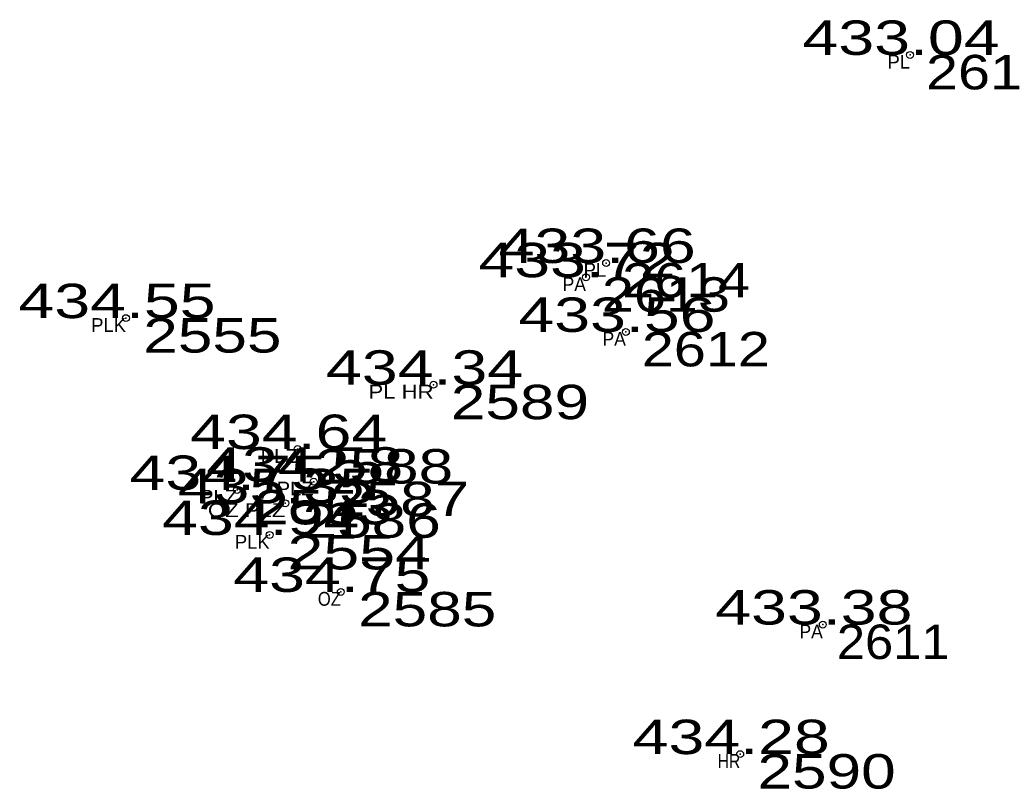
# Model space of a CAD drawing. Extents: x -639390 to -639074, y -1138747 to -1138358.
# Drawn here: x -639365.5 to -639343.8, y -1138399.35 to -1138382.61 of the extents above; entities that cross this region are included whole.
import ezdxf
from ezdxf.enums import TextEntityAlignment as Align

# ---------------------------------------------------------------- set-up
doc = ezdxf.new("R2010")
doc.units = 0
doc.header["$LTSCALE"] = 0.3
doc.header["$PDMODE"] = 32
doc.header["$PDSIZE"] = 0.15
for name, color, linetype in [('11', 7, 'Continuous'), ('12', 7, 'Continuous'), ('13', 7, 'Continuous'), ('57', 7, 'Continuous')]:
    doc.layers.add(name, color=color, linetype=linetype)

msp = doc.modelspace()

# ---------------------------------------------------------------- linework, layer by layer
at = {"layer": '11'}
for p in [(-639346.11, -1138383.37), (-639352.73, -1138387.9), (-639353.17, -1138388.21), (-639363.19, -1138389.1), (-639352.3, -1138389.4), (-639356.49, -1138390.55), (-639359.45, -1138391.95), (-639359.1, -1138392.66), (-639360.77, -1138392.84), (-639359.72, -1138393.13), (-639360.06, -1138393.82), (-639358.51, -1138395.06), (-639348.01, -1138395.77), (-639349.81, -1138398.59)]:
    msp.add_point(p, dxfattribs=at)

# ---------------------------------------------------------------- texts
at = {"layer": '12', "width": 1.4}
for s, p in [('433.04 ', (-639346.11, -1138383.37)), ('433.66 ', (-639352.729, -1138387.9)), ('433.72 ', (-639353.17, -1138388.21)), ('434.55 ', (-639363.19, -1138389.1)), ('433.56 ', (-639352.299, -1138389.4)), ('434.34 ', (-639356.49, -1138390.55)), ('434.64 ', (-639359.45, -1138391.95)), ('434.58 ', (-639359.1, -1138392.66)), ('434.75 ', (-639360.77, -1138392.84)), ('435.35 ', (-639359.72, -1138393.13)), ('434.94 ', (-639360.06, -1138393.82)), ('434.75 ', (-639358.51, -1138395.06)), ('433.38 ', (-639348.01, -1138395.77)), ('434.28 ', (-639349.81, -1138398.59))]:
    msp.add_text(s, height=0.75, dxfattribs=at).set_placement(p, align=Align.CENTER)
at = {"layer": '13'}
for s, width, p in [(' 2615', 1.25, (-639346.11, -1138384.12)), (' 2614', 1.25, (-639352.73, -1138388.65)), (' 2613', 1.25, (-639353.17, -1138388.96)), (' 2555', 1.35, (-639363.19, -1138389.85)), (' 2612', 1.25, (-639352.3, -1138390.15)), (' 2589', 1.35, (-639356.49, -1138391.3)), (' 2588', 1.35, (-639359.45, -1138392.7)), (' 2587', 1.35, (-639359.1, -1138393.41)), (' 2553', 1.35, (-639360.77, -1138393.59)), (' 2586', 1.35, (-639359.72, -1138393.88)), (' 2554', 1.4, (-639360.06, -1138394.57)), (' 2585', 1.35, (-639358.51, -1138395.81)), (' 2611', 1.1, (-639348.01, -1138396.52)), (' 2590', 1.35, (-639349.81, -1138399.34))]:
    msp.add_text(s, height=0.75, dxfattribs=dict(at, width=width)).set_placement(p)
at = {"layer": '57'}
for s, p in [('PL', (-639346.109, -1138383.67)), ('PL', (-639352.729, -1138388.2)), ('PLK', (-639363.189, -1138389.4)), ('PLK', (-639360.059, -1138394.12))]:
    msp.add_text(s, height=0.3, dxfattribs=at).set_placement(p, align=Align.RIGHT)
for s, width, p in [('PA', 0.95, (-639353.17, -1138388.51)), ('PA', 0.95, (-639352.3, -1138389.7)), ('PL HR', 1.2, (-639356.489, -1138390.85)), ('PLZ', 1.1, (-639359.449, -1138392.25)), ('PLZ', 1.1, (-639359.099, -1138392.96)), ('PLZ', 1.1, (-639360.769, -1138393.14)), ('OZ PLZ', 1.2, (-639359.719, -1138393.43)), ('OZ', 0.9, (-639358.509, -1138395.36)), ('PA', 0.95, (-639348.01, -1138396.07)), ('HR', 0.85, (-639349.809, -1138398.89))]:
    msp.add_text(s, height=0.3, dxfattribs=dict(at, width=width)).set_placement(p, align=Align.RIGHT)

doc.saveas('drawing.dxf')
